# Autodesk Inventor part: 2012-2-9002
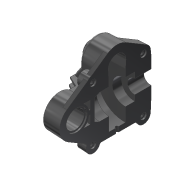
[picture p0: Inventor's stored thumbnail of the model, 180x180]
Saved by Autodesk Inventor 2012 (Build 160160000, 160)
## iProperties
Created: 2012-02
Part Number: 2012-2-9002
Material: Default
Document SubType Name: Modeling
Designer: jrr70267
Density: 1 g/cm^3
Description: Left Gear Box
Author: jrr70267
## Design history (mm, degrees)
derived "2012-2-9002.ipt"
feature "2012-2-9001::2012-2-9002.ipt" dims "d0" = 10
tag "TaggingFeature1"
body "Solid1"
